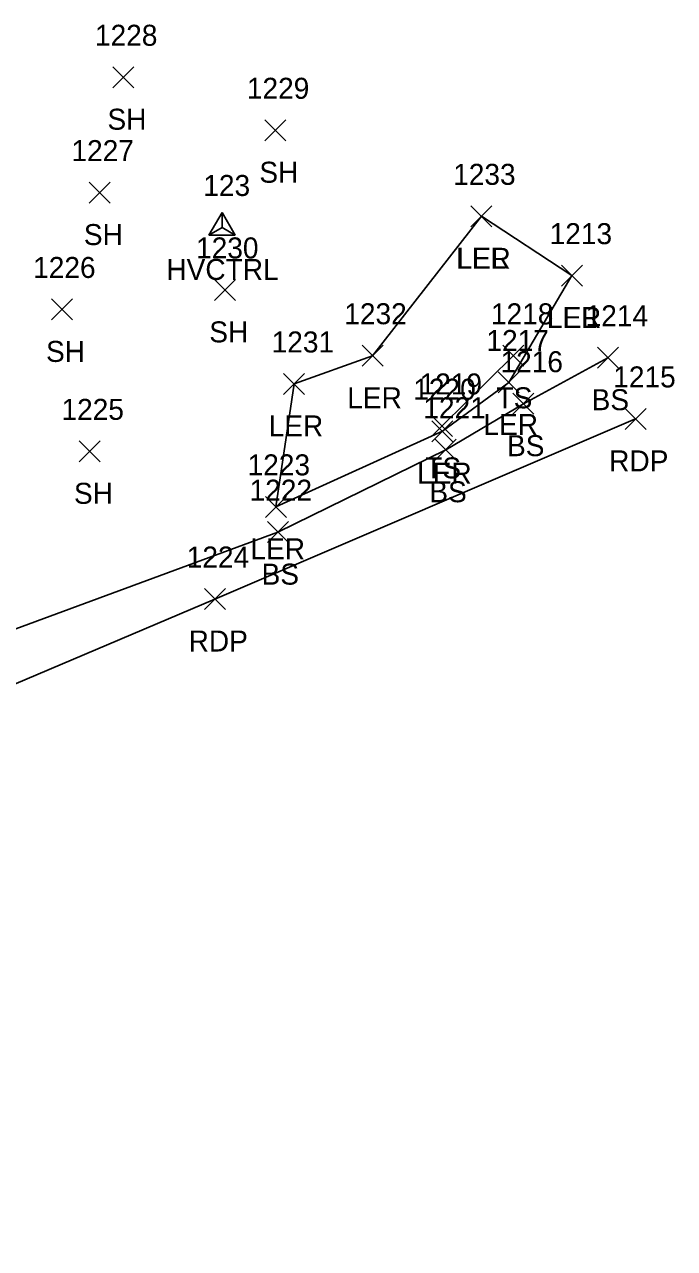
# Model space of a CAD drawing. Extents: x 1683147 to 1683637, y 416837 to 418211.
# Drawn here: x 1683386.3 to 1683448.2, y 417560.4 to 417677 of the extents above; entities that cross this region are included whole.
import ezdxf

# ---------------------------------------------------------------- set-up
doc = ezdxf.new("R2010")
doc.units = 0
for name, color, linetype in [('C_A', 7, 'Continuous'), ('C_I', 7, 'Continuous'), ('CPSM', 7, 'Continuous'), ('L_A', 7, 'Continuous'), ('L_I', 7, 'Continuous'), ('L_TIC', 7, 'Continuous'), ('LARO', 7, 'Continuous'), ('LELB', 7, 'Continuous'), ('P_A', 7, 'Continuous'), ('P_I', 7, 'Continuous'), ('P_TIC', 7, 'Continuous'), ('PET', 7, 'Continuous')]:
    doc.layers.add(name, color=color, linetype=linetype)

msp = doc.modelspace()

# ---------------------------------------------------------------- linework, layer by layer
at = {"layer": 'CPSM'}
for p, q in [((1683403.89, 417656.91), (1683405.14, 417659.08)), ((1683406.39, 417656.91), (1683405.14, 417659.08)), ((1683405.14, 417657.64), (1683405.14, 417659.08)), ((1683403.89, 417656.91), (1683405.14, 417657.64)), ((1683403.89, 417656.91), (1683406.39, 417656.91)), ((1683405.14, 417657.64), (1683405.14, 417657.64)), ((1683405.14, 417657.64), (1683406.39, 417656.91))]:
    msp.add_line(p, q, dxfattribs=at)
at = {"layer": 'L_TIC'}
for points in [[(1683394.73, 417670.95), (1683396.73, 417672.95)], [(1683396.73, 417670.95), (1683394.73, 417672.95)], [(1683409.2, 417665.9), (1683411.2, 417667.9)], [(1683411.2, 417665.9), (1683409.2, 417667.9)], [(1683392.49, 417659.96), (1683394.49, 417661.96)], [(1683394.49, 417659.96), (1683392.49, 417661.96)], [(1683428.84, 417657.7), (1683430.84, 417659.7)], [(1683430.84, 417657.7), (1683428.84, 417659.7)], [(1683428.84, 417657.7), (1683430.84, 417659.7)], [(1683430.84, 417657.7), (1683428.84, 417659.7)], [(1683437.46, 417652.05), (1683439.46, 417654.05)], [(1683439.46, 417652.05), (1683437.46, 417654.05)], [(1683437.46, 417652.05), (1683439.46, 417654.05)], [(1683439.46, 417652.05), (1683437.46, 417654.05)], [(1683404.43, 417650.69), (1683406.43, 417652.69)], [(1683406.43, 417650.69), (1683404.43, 417652.69)], [(1683388.89, 417648.83), (1683390.89, 417650.83)], [(1683390.89, 417648.83), (1683388.89, 417650.83)], [(1683418.48, 417644.42), (1683420.48, 417646.42)], [(1683420.48, 417644.42), (1683418.48, 417646.42)], [(1683431.87, 417644.41), (1683433.87, 417646.41)], [(1683433.87, 417644.41), (1683431.87, 417646.41)], [(1683440.9, 417644.23), (1683442.9, 417646.23)], [(1683442.9, 417644.23), (1683440.9, 417646.23)], [(1683410.99, 417641.73), (1683412.99, 417643.73)], [(1683412.99, 417641.73), (1683410.99, 417643.73)], [(1683431.45, 417641.87), (1683433.45, 417643.87)], [(1683433.45, 417641.87), (1683431.45, 417643.87)], [(1683432.84, 417639.85), (1683434.84, 417641.85)], [(1683434.84, 417639.85), (1683432.84, 417641.85)], [(1683425.09, 417637.73), (1683427.09, 417639.73)], [(1683427.09, 417637.73), (1683425.09, 417639.73)], [(1683425.13, 417637.23), (1683427.13, 417639.23)], [(1683427.13, 417637.23), (1683425.13, 417639.23)], [(1683391.54, 417635.31), (1683393.54, 417637.31)], [(1683393.54, 417635.31), (1683391.54, 417637.31)], [(1683425.44, 417635.46), (1683427.44, 417637.46)], [(1683427.44, 417635.46), (1683425.44, 417637.46)], [(1683409.26, 417630.02), (1683411.26, 417632.02)], [(1683411.26, 417630.02), (1683409.26, 417632.02)], [(1683409.46, 417627.61), (1683411.46, 417629.61)], [(1683411.46, 417627.61), (1683409.46, 417629.61)]]:
    msp.add_lwpolyline(points, dxfattribs=at)
at = {"layer": 'LARO'}
for points in [[(1683438.46, 417653.05), (1683432.45, 417642.87), (1683426.13, 417638.23), (1683410.26, 417631.02), (1683411.99, 417642.73), (1683419.48, 417645.42), (1683429.84, 417658.7)], [(1683438.46, 417653.05), (1683429.84, 417658.7)]]:
    msp.add_lwpolyline(points, dxfattribs=at)
at = {"layer": 'LELB'}
for points in [[(1683441.9, 417645.23), (1683433.84, 417640.85), (1683426.44, 417636.46), (1683410.46, 417628.61), (1683364.37, 417611.63), (1683314.71, 417595.12), (1683285.09, 417588.01)], [(1683432.87, 417645.41), (1683426.09, 417638.73)]]:
    msp.add_lwpolyline(points, dxfattribs=at)
at = {"layer": 'P_TIC'}
for points in [[(1683443.52, 417638.4), (1683445.52, 417640.4)], [(1683445.52, 417638.4), (1683443.52, 417640.4)], [(1683403.46, 417621.24), (1683405.46, 417623.24)], [(1683405.46, 417621.24), (1683403.46, 417623.24)]]:
    msp.add_lwpolyline(points, dxfattribs=at)
at = {"layer": 'PET'}
msp.add_lwpolyline([(1683444.52, 417639.4), (1683404.46, 417622.24), (1683363.8, 417604.98), (1683316.85, 417587.7), (1683293.07, 417578.55), (1683271.47, 417569.83), (1683261.72, 417567.45), (1683241.63, 417563.08), (1683221.13, 417560.36), (1683207.79, 417560.65)], dxfattribs=at)

# ---------------------------------------------------------------- texts
at = {"layer": 'C_A'}
msp.add_text('HVCTRL', height=2, dxfattribs=at).set_placement((1683399.83, 417652.64))
at = {"layer": 'C_I'}
msp.add_text('123', height=2, dxfattribs=at).set_placement((1683403.35, 417660.64))
at = {"layer": 'L_A'}
for s, p in [('SH', (1683394.22, 417666.95)), ('SH', (1683408.69, 417661.9)), ('SH', (1683391.97, 417655.96)), ('LER', (1683427.43, 417653.7)), ('LEL', (1683427.48, 417653.7)), ('LER', (1683436.05, 417648.05)), ('LEL', (1683436.1, 417648.05)), ('SH', (1683403.92, 417646.69)), ('SH', (1683388.37, 417644.83)), ('LER', (1683417.06, 417640.42)), ('TS', (1683431.28, 417640.41)), ('BS', (1683440.34, 417640.23)), ('LER', (1683409.57, 417637.73)), ('LER', (1683430.03, 417637.87)), ('BS', (1683432.28, 417635.85)), ('LER', (1683423.71, 417633.23)), ('TS', (1683424.49, 417633.73)), ('BS', (1683424.88, 417631.46)), ('SH', (1683391.03, 417631.31)), ('LER', (1683407.84, 417626.02)), ('BS', (1683408.9, 417623.61))]:
    msp.add_text(s, height=2, dxfattribs=at).set_placement(p)
at = {"layer": 'L_I'}
for s, p in [('1228', (1683393.03, 417674.95)), ('1229', (1683407.5, 417669.9)), ('1227', (1683390.79, 417663.96)), ('1233', (1683427.15, 417661.7)), ('1233', (1683427.15, 417661.7)), ('1213', (1683436.34, 417656.05)), ('1213', (1683436.34, 417656.05)), ('1230', (1683402.66, 417654.69)), ('1226', (1683387.14, 417652.83)), ('1232', (1683416.78, 417648.42)), ('1218', (1683430.75, 417648.41)), ('1214', (1683439.77, 417648.23)), ('1231', (1683409.86, 417645.73)), ('1217', (1683430.32, 417645.87)), ('1216', (1683431.66, 417643.85)), ('1220', (1683423.35, 417641.23)), ('1219', (1683423.95, 417641.73)), ('1225', (1683389.84, 417639.31)), ('1221', (1683424.31, 417639.46)), ('1223', (1683407.57, 417634.02)), ('1222', (1683407.76, 417631.61))]:
    msp.add_text(s, height=2, dxfattribs=at).set_placement(p)
at = {"layer": 'P_A'}
for p in [(1683442.01, 417634.4), (1683401.95, 417617.24)]:
    msp.add_text('RDP', height=2, dxfattribs=at).set_placement(p)
at = {"layer": 'P_I'}
for s, p in [('1215', (1683442.4, 417642.4)), ('1224', (1683401.77, 417625.24))]:
    msp.add_text(s, height=2, dxfattribs=at).set_placement(p)

doc.saveas('drawing.dxf')
